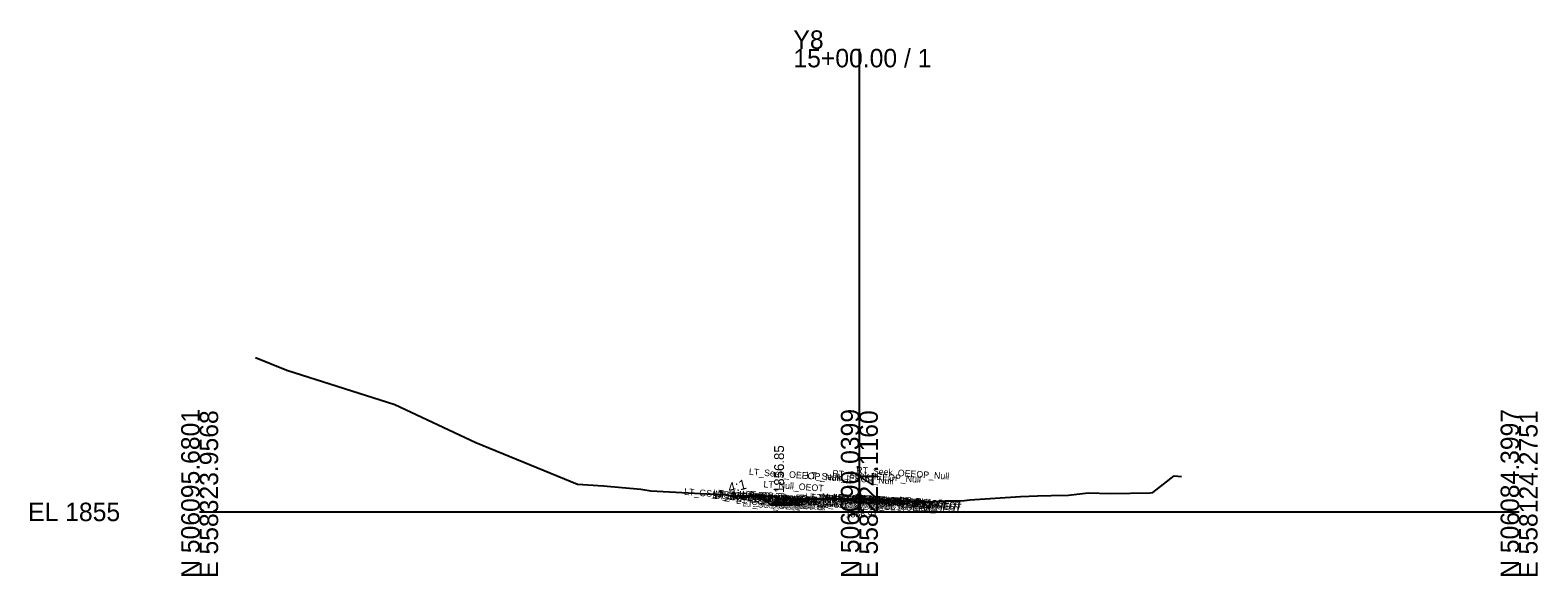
# Model space of a CAD drawing. Extents: x -26 to 203, y -10 to 8070.
# Drawn here: x -25.7 to 202.8, y 4990.3 to 5073 of the extents above; entities that cross this region are included whole.
import ezdxf

# ---------------------------------------------------------------- set-up
doc = ezdxf.new("R2010")
doc.units = 0
for name, color, linetype in [('Default', 7, 'Continuous'), ('Exist Cross Section Cell', 7, 'Continuous'), ('Exist XS Center Line Elevation Label', 7, 'Continuous'), ('Exist XS Ground Line', 7, 'Continuous'), ('Prop CMT Conc Surface', 7, 'Continuous'), ('Prop CMT Concrete Structures', 7, 'Continuous'), ('Prop CMT Pvmt Course 1', 7, 'Continuous'), ('Prop CMT Pvmt Course 1 CG', 7, 'Continuous'), ('Prop CMT Pvmt Course 2', 7, 'Continuous'), ('Prop CMT Pvmt Course 3', 7, 'Continuous'), ('Prop CMT Pvmt Surface', 7, 'Continuous'), ('Prop CMT Slope Grass', 7, 'Continuous'), ('Prop CMT Subgrade Earthwork', 7, 'Continuous'), ('Prop XS Earthwork Shape', 7, 'Continuous'), ('Prop XS Hydro Elevations', 7, 'Continuous'), ('Prop XS Side Slope Text', 7, 'Continuous'), ('Typical Text Grade Point CELL', 7, 'Continuous')]:
    doc.layers.add(name, color=color, linetype=linetype)

msp = doc.modelspace()

# ---------------------------------------------------------------- linework, layer by layer
at = {"layer": 'Exist Cross Section Cell'}
for p, q in [((100, 5000), (100, 5070.19)), ((0, 5000), (100, 5000)), ((100, 5000), (200, 5000))]:
    msp.add_line(p, q, dxfattribs=at)
at = {"layer": 'Exist XS Ground Line'}
for p, q in [((8.45, 5023.4), (13.2, 5021.48)), ((13.2, 5021.48), (29.59, 5016.3)), ((29.59, 5016.3), (41.84, 5010.51)), ((41.84, 5010.51), (57.27, 5004.22)), ((144.47, 5002.92), (147.71, 5005.45)), ((147.71, 5005.45), (148.81, 5005.35)), ((57.27, 5004.22), (61.2, 5003.97)), ((61.2, 5003.97), (66.87, 5003.45)), ((66.87, 5003.45), (68.4, 5003.2)), ((68.4, 5003.2), (79.69, 5002.59)), ((79.69, 5002.59), (82.14, 5002.3)), ((131.7, 5002.54), (134.69, 5002.91)), ((134.69, 5002.91), (138.04, 5002.79)), ((138.04, 5002.79), (144.09, 5002.89)), ((144.09, 5002.89), (144.47, 5002.92)), ((82.14, 5002.3), (82.82, 5002.28)), ((82.82, 5002.28), (87.22, 5002.37)), ((87.22, 5002.37), (87.82, 5001.91)), ((87.82, 5001.91), (89.45, 5001.93)), ((89.45, 5001.93), (98.69, 5001.92)), ((98.69, 5001.92), (100, 5001.91)), ((100, 5001.91), (100.39, 5001.91)), ((100.39, 5001.91), (109.1, 5001.56)), ((109.1, 5001.56), (110.56, 5001.51)), ((110.56, 5001.51), (111.14, 5001.56)), ((111.14, 5001.56), (113.21, 5001.7)), ((113.21, 5001.7), (115.3, 5001.7)), ((115.3, 5001.7), (115.91, 5001.72)), ((115.91, 5001.72), (116.75, 5001.81)), ((116.75, 5001.81), (124.42, 5002.35)), ((124.42, 5002.35), (127.01, 5002.46)), ((127.01, 5002.46), (129.09, 5002.51)), ((129.09, 5002.51), (131.7, 5002.54))]:
    msp.add_line(p, q, dxfattribs=at)
at = {"layer": 'Prop CMT Conc Surface'}
for points in [[(87.83, 5001.85), (87.82, 5002.35), (87.32, 5002.35)], [(89.83, 5001.93), (87.83, 5001.85)]]:
    msp.add_lwpolyline(points, dxfattribs=at)
at = {"layer": 'Prop CMT Concrete Structures'}
for points in [[(89.83, 5001.93), (87.83, 5001.85), (87.82, 5002.35), (87.32, 5002.35)], [(87.32, 5002.35), (87.33, 5001.35), (89.83, 5001.35)], [(89.83, 5001.35), (89.83, 5001.93)]]:
    msp.add_lwpolyline(points, dxfattribs=at)
at = {"layer": 'Prop CMT Pvmt Course 1'}
for points in [[(100, 5001.91), (98, 5001.92), (97.99, 5001.92), (89.69, 5001.93), (89.68, 5001.93)], [(89.68, 5001.93), (89.83, 5001.93)], [(89.83, 5001.93), (89.83, 5001.68), (89.83, 5001.68), (89.83, 5001.81)], [(100, 5001.91), (102, 5001.85), (102.01, 5001.85), (105.99, 5001.69), (106, 5001.69), (110.17, 5001.52)]]:
    msp.add_lwpolyline(points, dxfattribs=at)
at = {"layer": 'Prop CMT Pvmt Course 1 CG'}
for points in [[(89.83, 5001.35), (86.83, 5001.35), (86.53, 5001.06)], [(86.53, 5001.06), (89.83, 5001.06)], [(89.83, 5001.06), (89.83, 5001.35)]]:
    msp.add_lwpolyline(points, dxfattribs=at)
at = {"layer": 'Prop CMT Pvmt Course 2'}
for points in [[(89.83, 5001.43), (89.83, 5001.43), (89.83, 5001.68), (89.83, 5001.68)], [(89.83, 5001.68), (89.83, 5001.43)]]:
    msp.add_lwpolyline(points, dxfattribs=at)
at = {"layer": 'Prop CMT Pvmt Course 3'}
for points in [[(89.83, 5001.43), (89.83, 5001.43), (89.83, 5001.06), (89.83, 5001.06)], [(89.83, 5001.06), (89.83, 5001.43)]]:
    msp.add_lwpolyline(points, dxfattribs=at)
at = {"layer": 'Prop CMT Pvmt Surface'}
for points in [[(100, 5001.91), (98, 5001.92), (97.99, 5001.92), (89.69, 5001.93), (89.68, 5001.93)], [(89.68, 5001.93), (89.83, 5001.93)], [(100, 5001.91), (102, 5001.85), (102.01, 5001.85), (105.99, 5001.69), (106, 5001.69), (110.17, 5001.52)]]:
    msp.add_lwpolyline(points, dxfattribs=at)
at = {"layer": 'Prop CMT Slope Grass'}
msp.add_lwpolyline([(87.32, 5002.35), (81.82, 5002.46), (81.45, 5002.37)], dxfattribs=at)
for centre in [(110.52, 5001.48), (112.61, 5001.64)]:
    msp.add_circle(centre, 0.00802, dxfattribs=at)
at = {"layer": 'Prop CMT Subgrade Earthwork'}
msp.add_line((91.33, 5001.05), (91.33, 5001.93), dxfattribs=at)
for points in [[(91.33, 5001.05), (86.53, 5001.06), (85.2, 5002.4)], [(89.83, 5001.06), (89.83, 5001.06)]]:
    msp.add_lwpolyline(points, dxfattribs=at)
at = {"layer": 'Prop XS Earthwork Shape'}
for points in [[(82.14, 5002.3), (82.82, 5002.28), (85.26, 5002.33), (85.2, 5002.4), (81.82, 5002.46), (81.49, 5002.38)], [(89.83, 5001.93), (87.83, 5001.85), (89.45, 5001.93), (89.68, 5001.93)], [(100, 5001.91), (100.39, 5001.91), (102, 5001.85)]]:
    msp.add_lwpolyline(points, close=True, dxfattribs=at)

# ---------------------------------------------------------------- texts
at = {"layer": 'Default'}
msp.add_text('-', height=0.0001, dxfattribs=at).set_placement((0, 5000))
at = {"layer": 'Exist Cross Section Cell'}
for s, p in [('Y8', (90, 5070.19)), ('15+00.00 / 1', (90, 5067.39)), ('EL 1855', (-26, 4998.6))]:
    msp.add_text(s, height=2.8, dxfattribs=at).set_placement(p)
for s, p in [('N 506095.6801', (0, 4990)), ('E 558323.9568', (2.8, 4990)), ('N 506090.0399', (100, 4990)), ('E 558224.1160', (102.8, 4990)), ('N 506084.3997', (200, 4990)), ('E 558124.2751', (202.8, 4990))]:
    msp.add_text(s, height=2.8, rotation=90, dxfattribs=at).set_placement(p)
at = {"layer": 'Exist XS Center Line Elevation Label'}
msp.add_text('1856.91', height=1, dxfattribs=at).set_placement((97.91, 4999.17))
at = {"layer": 'Prop XS Hydro Elevations'}
msp.add_text('1856.85', height=1.5, rotation=90, dxfattribs=at).set_placement((88.58, 5002.85))
at = {"layer": 'Prop XS Side Slope Text'}
msp.add_text('4:1', height=1.5, rotation=14.0362, dxfattribs=at).set_placement((80.3, 5002.86))
at = {"layer": 'Typical Text Grade Point CELL'}
for s, p in [('LT_Seek_OEEOP_Null', (83.23, 5005.61)), ('LT_Seek_IEEOP_Null', (91.93, 5005.09)), ('RT_Seek_IEEOP_Null', (95.87, 5005.34)), ('RT_Seek_OEEOP_Null', (99.49, 5005.87)), ('LT_GS_OS_GR_Face_Graphics', (73.41, 5002.58)), ('LT_Slope_Fill', (77.67, 5002.13)), ('LT_Sub_Trench_Out_DLT', (77.83, 5002.41)), ('LT_GS_OS_GR_Face_Graphics1', (78, 5002)), ('LT_CSLP_Pnt', (78.1, 5002.22)), ('LT_CG_MatchPVSlope_Null', (79.75, 5002)), ('LT_CG_Top_BOC', (82.21, 5002.21)), ('LT_CG_Top_Face', (82.72, 5002.21)), ('LT_CG_Top_Gut', (82.99, 5001.69)), ('LT_PV_Sub_Tie_Out', (83.83, 5001.84)), ('LT_Null OEEOP Test', (84.08, 5001.86)), ('LT_PV1_OEEOP', (85.31, 5001.62)), ('LT_Null_OEOT', (85.44, 5003.72)), ('LT_PV1_OEOT', (85.67, 5001.72)), ('LT_Pvmt Out', (85.93, 5001.69)), ('LT_Null IEEOP Test', (91.78, 5001.82)), ('LT_PV_Sub_Tie_In', (92.76, 5001.78)), ('Null RT Pvmt Slope', (94.26, 5001.83)), ('Null LT Pvmt Slope', (94.32, 5001.81)), ('PV1_Overlay_Null', (94.75, 5001.65)), ('LT_Pvmt In', (94.84, 5001.64)), ('RT_PV_Sub_Tie_In', (96.7, 5001.72)), ('RT_Null IEEOP Test', (96.72, 5001.73)), ('PV1_PGL', (97.44, 5001.59)), ('RT_Null OEEOP Test', (99.34, 5001.64)), ('RT_PV_Sub_Tie_Out', (100.09, 5001.6)), ('LT_CG1_Shelf_Out', (81.29, 5001.24)), ('LT_Sub_OEOP', (82.27, 5000.86)), ('LT_CG_Bot_BOC', (82.35, 5001.2)), ('LT_PV2_OEEOP', (85.19, 5001.5)), ('LT_PV3_OEEOP', (85.19, 5001.25)), ('LT_Sub_OEEOP', (85.22, 5000.88)), ('LT_PV2_OEOT', (85.55, 5001.48)), ('LT_PV3_OEOT', (85.55, 5001.23)), ('LT_Sub_OEOT', (85.57, 5000.85)), ('LT_CG_Bot_IE', (85.72, 5001.13)), ('LT_PV2_IEEOP', (93.75, 5001.46)), ('LT_PV3_IEEOP', (93.75, 5001.21)), ('LT_Sub_IEEOP', (93.77, 5000.84)), ('LT_PV1_IEEOP', (93.87, 5001.58)), ('Sub_PGL', (97.35, 5000.72)), ('PV2_PGL', (97.32, 5001.35)), ('PV3_PGL', (97.32, 5001.1)), ('RT_PV2_IEEOP', (97.69, 5001.39)), ('RT_PV3_IEEOP', (97.69, 5001.14)), ('RT_Sub_IEEOP', (97.71, 5000.76)), ('RT_PV1_IEEOP', (97.81, 5001.5)), ('RT_Pvmt In', (98.8, 5001.57)), ('CL', (99.2, 5001.47)), ('RT_PV2_OEEOP', (101.31, 5001.26)), ('RT_PV3_OEEOP', (101.31, 5001.01)), ('RT_Sub_OEEOP', (101.33, 5000.63)), ('RT_PV1_OEEOP', (101.43, 5001.37)), ('RT_Pvmt Out', (102.17, 5001.45)), ('RT_PV2_OEOT', (105.84, 5001.07)), ('RT_PV3_OEOT', (105.84, 5000.82)), ('RT_Sub_OEOT', (105.86, 5000.44)), ('RT_PV1_OEOT', (105.96, 5001.31))]:
    msp.add_text(s, height=1, rotation=356, dxfattribs=at).set_placement(p)

doc.saveas('drawing.dxf')
